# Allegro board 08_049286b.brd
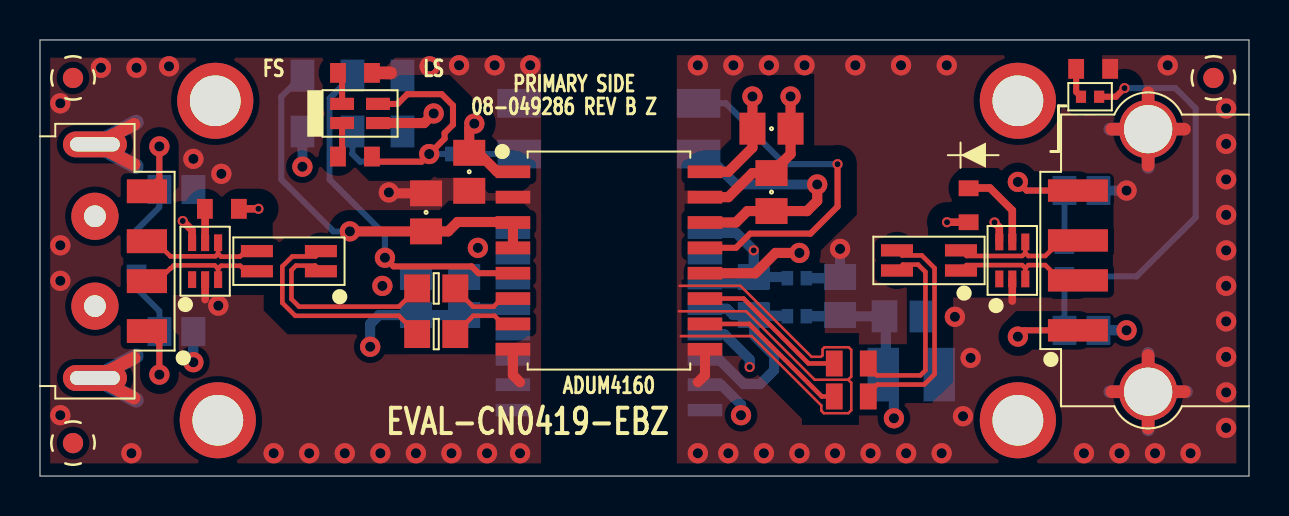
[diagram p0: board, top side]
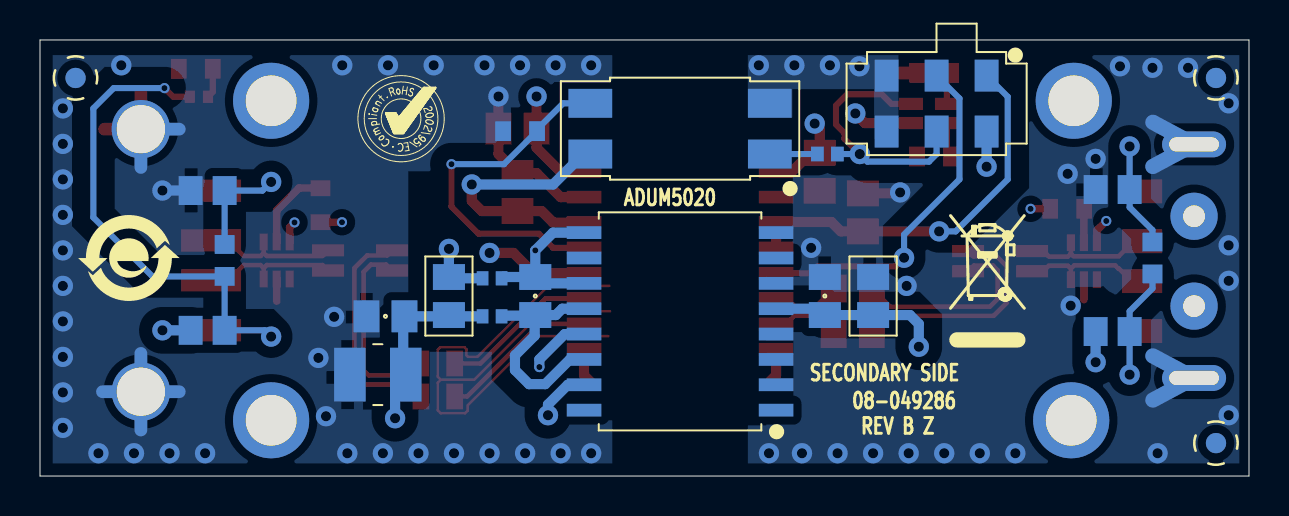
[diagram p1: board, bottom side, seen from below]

Outline 60.45 x 21.84 mm; copper layers: TOP, L2_GND, L3_VCC, BOTTOM. Coordinates in mm from the lower left corner of the outline.
Outline path: 0,21.84 0,0 60.45,0 60.45,21.84 0,21.84

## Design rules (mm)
constraint set DEFAULT: min track width 0.127
net group DP1: nets UNNAMED_2_CHOKE4P_I81_N2 UNNAMED_2_CHOKE4P_I81_N3
net group DP2: nets UNNAMED_2_CHOKE4P_I82_N1 UNNAMED_2_CHOKE4P_I82_N4
net group UNNAMED_2_ADUM4160_I1_DD: nets UNNAMED_2_ADUM4160_I1_DDNEG UNNAMED_2_ADUM4160_I1_DDPOS
net group UNNAMED_2_ADUM4160_I1_UD: nets UNNAMED_2_ADUM4160_I1_UDNEG UNNAMED_2_ADUM4160_I1_UDPOS
net group USB_DIFF_A: nets UNNAMED_2_CHOKE4P_I82_N2 UNNAMED_2_CHOKE4P_I82_N3
net group USB_DIFF_B: nets UNNAMED_2_CN4P2PSHLDV2_I66_N2 UNNAMED_2_CN4P2PSHLDV2_I66_N3

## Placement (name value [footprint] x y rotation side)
C1  0.001uF  [C0603]  4.83 10.92 270 bottom
C2  10uF  [C0805H53]  18.8 9.02 90 bottom
C3  0.1UF  [C0805]  21.21 9.02 90 bottom
C4  0.1UF  [C0805]  21.46 15.24 270 top
C5  0.1UF  [C0805]  19.3 13.21 270 top
C7  0.1UF  [C0805]  35.69 9.02 90 bottom
C8  0.1UF  [C0805]  36.58 17.4 0 top
C9  0.1UF  [C0805]  36.58 14.22 270 top
C10  10uF  [C0805H53]  40 9.02 90 bottom
C11  0.1UF  [C0805]  43.18 8 0 bottom
C12  100UF  [C1210-2]  43.56 5.08 180 bottom
C19  0.001uF  [C0603]  51.22 10.8 270 bottom
D1  RCLAMP0504FBTCT  [SC70-6H43]  8.26 10.76 0 top
D2  RCLAMP0504FBTCT  [SC70-6H43]  48.62 10.8 0 top
D3  LTV-817S-TA1  [SOP4H181]  28.45 17.4 90 bottom
D4  APHBM2012LVBDZGKC  [LED0805_4P]  16 18.16 180 top
DS1  SML-P11MTT86  [LED0402]  52.5 19 0 top
E1  220OHM  [L0805]  6.82 14.35 0 bottom
E2  220OHM  [L0805]  6.82 7.24 0 bottom
E3  220OHM  [L0805]  52.07 7.3 180 bottom
E4  220OHM  [L0805]  52.07 14.3 180 bottom
E5  1.8K AT 100MEGHZ  [L0402]  37.85 8 0 bottom
E6  1.8K AT 100MEGHZ  [L0402]  37.85 9.91 0 bottom
L1  260OHM AT 100MEGHZ  [LSML63W126H79]  12.45 10.76 90 top
L2  260OHM AT 100MEGHZ  [LSML63W126H79]  44.45 10.8 90 top
NOREF  -  []  -46.99 -67.82 0 top
NOREF#2  -  []  80.33 313.16 0 top
NOREF#3  -  []  -201.19 -168.4 0 top
NOREF#4  -  []  -39.37 155.07 0 top
NOREF#5  -  []  65.79 21.84 180 top
NOREF#6  -  []  0 10.74 0 top
NOREF#7  -  []  0 21.84 270 top
NOREF#8  -  [unnamed#2]  1.65 19.94 0 top
NOREF#9  -  [unnamed#2]  48.9 18.8 0 top
NOREF#10  -  []  8.89 2.79 0 top
NOREF#11  -  [unnamed#2]  8.89 2.79 0 top
NOREF#12  -  []  0 0 0 top
NOREF#13  -  []  60.45 0 0 top
NOREF#14  -  []  137.18 95.95 0 top
NOREF#15  -  [unnamed#2]  58.67 19.94 0 top
NOREF#16  -  []  0 0 0 top
NOREF#17  -  []  81.38 262.84 0 top
NOREF#18  -  []  0 21.84 0 top
NOREF#19  -  []  112.97 125.48 0 top
NOREF#20  -  []  8.89 2.79 0 top
NOREF#21  -  []  65.79 0 90 top
NOREF#22  -  []  60.45 0 90 top
NOREF#23  -  []  0 0 0 top
NOREF#24  -  []  28.45 35.48 0 top
NOREF#25  -  []  0 21.84 0 top
NOREF#26  -  [unnamed#2]  1.65 1.65 0 top
NOREF#27  -  []  -47.17 -68.07 0 top
NOREF#28  -  [unnamed#2]  48.9 2.79 0 top
NOREF#29  -  [unnamed#2]  8.76 18.8 0 top
NOREF#30  -  [unnamed#2]  1.65 1.65 180 bottom
NOREF#31  -  []  56.01 10.92 180 bottom
NOREF#32  -  [unnamed#2]  58.67 19.94 180 bottom
NOREF#33  -  []  13.28 6.5 180 bottom
NOREF#34  -  [unnamed#2]  1.65 19.94 180 bottom
P1  48037-2200  [CNMOLEX48037-2200]  2.75 10.76 90 top
P2  62900416021  [CNWURTH62900416021]  58.51 10.8 90 top
R1  10K  [R0603]  9.09 13.39 180 top
R2  24  [R0805#2]  19.81 9.4 0 top
R3  24  [R0805#2]  19.81 7.11 0 top
R4  24  [R0805]  40.56 5.64 0 top
R5  24  [R0805]  40.56 3.99 0 top
R6  10K  [R0603]  46.43 13.56 90 top
R7  301  [R0402]  21.08 16.13 0 bottom
R8  10K  [R0603]  36.45 17.27 180 bottom
R9  2.55K  [R0603]  15.75 20.19 0 top
R10  2.55K  [R0603]  15.75 16 0 top
R11  6.2K  [R0603]  52.66 20.4 0 top
S1  CL-SB-22A-11T  [SWSML335W138H217]  15.62 18.66 0 bottom
U1  ADUM4160BRWZ  [SO16WB]  28.45 10.79 270 top
U2  ADUM5020-5BRWZ  [SO16WB]  28.45 7.75 90 bottom

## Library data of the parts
C1 C19 = CAP: User Part Number: UPN; Tolerance: 5; alternate symbols: (C0603L_ALT); part number: CAP_SM-0.001UF,50V,5,E007908,C0603; tolerance: 5
C2 C10 = CAP: Tolerance: 10; User Part Number: UPN; alternate symbols: (); part number: CAP_SM-10UF,16V,10,E006166,C0805H53; tolerance: 10
C3-C5 C7-C9 C11 = CAP: Tolerance: 5; User Part Number: UPN; alternate symbols: (); part number: CAP_SM-0.1UF,50V,5,E031467,C0805; tolerance: 5
C12 = CAP: Tolerance: 20; User Part Number: UPN; alternate symbols: (); part number: CAP_SM-100UF,6.3V,20,E031805,C1210-2; tolerance: 20
D1 D2 = DIO6P_V9: User Part Number: UPN; Tolerance: N/A; alternate symbols: (); part number: DIO6P_V9_SM-RCLAMP0504FBTCT,5V,N/A,E031729,SC70-6H43; tolerance: N/A
D3 = DIOPHOTO_V4: User Part Number: UPN; Tolerance: N/A; alternate symbols: (); part number: DIOPHOTO_V4_SM-LTV-817S-TA1,35V,N/A,E033100,SOP4H181; tolerance: N/A
D4 = DIOLED_4P_V17: Tolerance: N/A; User Part Number: UPN; alternate symbols: (); part number: DIOLED_4P_V17_SM-APHBM2012LVBDZGKC,2.7V,N/A,E033594,LED0805_4P; tolerance: N/A
DS1 = DIOLED: User Part Number: UPN; Tolerance: N/A; alternate symbols: (); part number: DIOLED_SM-SML-P11MTT86,N/A,N/A,E014445,LED0402; tolerance: N/A
E1-E4 = FERRITE: User Part Number: UPN; Tolerance: 25; alternate symbols: (); part number: FERRITE_SM-220OHM,25,E017491,L0805; tolerance: 25
E5 E6 = FERRITE: User Part Number: UPN; Tolerance: 25; alternate symbols: (); part number: FERRITE_SM-1.8K AT 100MEGHZ,25,E027761,L0402; tolerance: 25
L1 L2 = CHOKE4P: User Part Number: UPN; Tolerance: 25; alternate symbols: (); part number: CHOKE4P_SM-260OHM AT 100MEGHZ,25,E027672,LSML63W126H79; tolerance: 25
P1 = CN4P_2PGND: User Part Number: UPN; Tolerance: N/A; alternate symbols: (); part number: CN4P_2PGND_SM-48037-2200,E028044,CNMOLEX48037-2200; tolerance: N/A
P2 = CN4P_2PSHLD_V2: Tolerance: N/A; User Part Number: UPN; alternate symbols: (); part number: CN4P_2PSHLD_V2_SM-62900416021,E024379,CNWURTH62900416021; tolerance: N/A
R1 R6 R8 = RES: User Part Number: UPN; Tolerance: 1; alternate symbols: (R0603L); part number: RES_SM-10K,E003671,1/10W,1,R0603; tolerance: 1
R2 R3 = RES: Tolerance: 1; User Part Number: UPN; alternate symbols: (); part number: RES_SM-24,E031456,1/8W,1,R0805; tolerance: 1
R4 R5 = RES: User Part Number: UPN; Tolerance: 1; alternate symbols: R0805L; part number: RES_SM-24,E031456,1/8W,1,R0805; tolerance: 1
R7 = RES: User Part Number: UPN; Tolerance: 1; alternate symbols: (R0402L); part number: RES_SM-301,E011195,1/16W,1,R0402; tolerance: 1
R9 R10 = RES: User Part Number: UPN; Tolerance: 1; alternate symbols: (); part number: RES_SM-2.55K,E032494,1/10W,1,R0603; tolerance: 1
R11 = RES: User Part Number: UPN; Tolerance: 1; alternate symbols: (R0603L); part number: RES_SM-6.2K,E010158,1/10W,1,R0603; tolerance: 1
S1 = SWDPDT_V5: User Part Number: UPN; Tolerance: N/A; alternate symbols: (); part number: SWDPDT_V5_SM-CL-SB-22A-11T,E033164,SWSML335W138H217; tolerance: N/A
U1 = ADUM4160: Tolerance: N/A; User Part Number: UPN; alternate symbols: (); part number: ADUM4160_SM-ADUM4160BRWZ,E012088,SO16WB; tolerance: N/A
U2 = ADUM5020: Tolerance: N/A; User Part Number: UPN; alternate symbols: (); part number: ADUM5020_SM-ADUM5020-5BRWZ,E028567,SO16WB; tolerance: N/A

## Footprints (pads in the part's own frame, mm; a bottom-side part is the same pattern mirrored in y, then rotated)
C0603
  rect 0.94x0.991 smd: 1(-0.8,0) 2(0.8,0)
C0805
  rect 1.295x1.6 smd: 1(-0.953,0) 2(0.953,0)
C0805H53
  rect 1.295x1.6 smd: 1(-0.953,0) 2(0.953,0)
C1210-2
  rect 1.575x2.692 smd: 1(-1.397,0) 2(1.397,0)
CNMOLEX48037-2200
  round 2.362 hole 1.092 unplated: (-2.25,0) (2.25,0)
  rect 1.194x2.007 smd: 1(-3.5,-2.6) 2(-1,-2.6) 3(1,-2.6) 4(3.5,-2.6)
  oval 1.295x3.2 hole 0.711x2.489: G1(-5.85,0) G2(5.85,0)
CNWURTH62900416021
  rect 1.118x2.997 smd: 1(-3.5,6.61) 2(-1,6.61) 3(1,6.61) 4(3.5,6.61)
  round 2.921 hole 2.413: SH1(-6.575,3.1) SH2(6.575,3.1)
L0402
  rect 0.584x0.711 smd: 1(-0.475,0) 2(0.475,0)
L0805
  rect 1.194x1.448 smd: 1(-0.85,0) 2(0.85,0)
LED0402
  rect 0.508x0.61 smd: A(0.454,0) C(-0.454,0)
LED0805_4P
  rect 1.194x0.61 smd: 1(-0.897,-0.48) 2(0.897,-0.48) 3(0.897,0.48) 4(-0.897,0.48)
LSML63W126H79
  rect 0.61x1.6 smd: 1(-0.505,-1.6) 2(-0.505,1.6) 3(0.505,1.6) 4(0.505,-1.6)
R0402
  rect 0.635x0.737 smd: 1(-0.5,0) 2(0.5,0)
R0603
  rect 0.787x0.991 smd: 1(-0.85,0) 2(0.85,0)
R0805
  rect 0.838x1.295 smd: 1(-0.85,0) 2(0.85,0)
R0805#2
  rect 1.295x1.397 smd: 1(-0.953,0) 2(0.953,0)
SC70-6H43
  rect 0.406x0.838 smd: 1(-0.65,-0.925) 2(0,-0.925) 3(0.65,-0.925) 4(0.65,0.925) 5(0,0.925) 6(-0.65,0.925)
SO16WB
  rect 0.635x1.727 smd: 1(-4.445,-4.801) 2(-3.175,-4.801) 3(-1.905,-4.801) 4(-0.635,-4.801) 5(0.635,-4.801) 6(1.905,-4.801) 7(3.175,-4.801) 8(4.445,-4.801) 9(4.445,4.801) 10(3.175,4.801) 11(1.905,4.801) 12(0.635,4.801) 13(-0.635,4.801) 14(-1.905,4.801) 15(-3.175,4.801) 16(-4.445,4.801)
SOP4H181
  rect 1.448x2.184 smd: 1(-1.27,-4.487) 2(1.27,-4.487) 3(1.27,4.487) 4(-1.27,4.487)
SWSML335W138H217
  rect 1.194x1.6 smd: 1(-2.5,-1.4) 2(0,-1.4) 3(2.5,-1.4) 4(-2.5,1.4) 5(0,1.4) 6(2.5,1.4)
unnamed#2
  round 1.016 smd: (0,0)

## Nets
5V_BUS: C2.1 C3.1 C4.1 D1.6 D4.4 E2.2(N2) R1.1 S1.4 U1.1 U2.5
5V_ISO_BUS: C8.1 C10.1 C11.1 C12.2(N2) D2.6 E3.1 E5.2(N2) R6.1 U1.16
AGND: C7.2(N2) E6.1 U2.9 U2.11 U2.13 U2.15
GND: C2.2(N2) C3.2(N2) C4.2(N2) C5.1 D1.2 D3.2 E1.2(N2) P1.G1 P1.G2 R9.2(N2) S1.3 S1.6(NO2) U1.2 U1.8 U2.2 U2.3 U2.4 U2.6 U2.8
GND_ISO: C8.2(N2) C9.1 C10.2(N2) C11.2(N2) C12.1 D2.2 E4.1 E6.2(N2) P2.SH1 P2.SH2(N6) R8.1 R11.2(N2) U1.9 U1.15
UNNAMED_2_ADUM4160_I1_DDNEG: R4.1 U1.11
UNNAMED_2_ADUM4160_I1_DDPOS: R5.1 U1.10
UNNAMED_2_ADUM4160_I1_PDEN: C5.2(N2) S1.1 U1.3 U1.4
UNNAMED_2_ADUM4160_I1_PIN: C9.2(N2) D3.4 U1.12 U1.14(VDD2)
UNNAMED_2_ADUM4160_I1_SPU: S1.2 U1.5
UNNAMED_2_ADUM4160_I1_UDNEG: R2.2(N2) U1.6
UNNAMED_2_ADUM4160_I1_UDPOS: R3.2(N2) U1.7
UNNAMED_2_ADUM5020_I2_VISO: C7.1 E5.1 U2.12 U2.14(VSEL)
UNNAMED_2_CAP_I84_N1: C1.1 E1.1 P1.4(N4)
UNNAMED_2_CAP_I84_N2: C1.2(N2) E2.1 P1.1
UNNAMED_2_CAP_I85_N1: C19.1 E4.2(N2) P2.4
UNNAMED_2_CAP_I85_N2: C19.2(N2) DS1.A(P) E3.2(N2) P2.1
UNNAMED_2_CHOKE4P_I81_N2: L2.2 R4.2(N2)
UNNAMED_2_CHOKE4P_I81_N3: L2.3 R5.2(N2)
UNNAMED_2_CHOKE4P_I82_N1: L1.1 R2.1
UNNAMED_2_CHOKE4P_I82_N2: D1.3 L1.2 P1.2
UNNAMED_2_CHOKE4P_I82_N3: D1.4 L1.3 P1.3
UNNAMED_2_CHOKE4P_I82_N4: L1.4(N4) R3.1
UNNAMED_2_CN4P2PSHLDV2_I66_N2: D2.3 L2.1 P2.2
UNNAMED_2_CN4P2PSHLDV2_I66_N3: D2.4 L2.4(N4) P2.3
UNNAMED_2_DIO6PV9_I78_VDD: D1.5(VDD) R1.2(N2)
UNNAMED_2_DIO6PV9_I79_VDD: D2.5(VDD) R6.2(N2)
UNNAMED_2_DIOLED4PV17_I106_A1: D4.1 R7.1 R10.2(N2) S1.5
UNNAMED_2_DIOLED4PV17_I106_C1: D4.2 R9.1
UNNAMED_2_DIOLED4PV17_I106_C2: D4.3(C2) R10.1
UNNAMED_2_DIOLED_I109_N: DS1.C R11.1
UNNAMED_2_DIOPHOTOV4_I98_A: D3.1 R7.2(N2)
UNNAMED_2_DIOPHOTOV4_I98_E: D3.3(E) R8.2(N2) U1.13

Pads without a net: D1 1; D2 1; U2 1 7 10 16

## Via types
v1: diameter 1.016, hole 0.508, TOP to BOTTOM, 80 vias
v2: diameter 0.508, hole 0.305, TOP to BOTTOM, 8 vias

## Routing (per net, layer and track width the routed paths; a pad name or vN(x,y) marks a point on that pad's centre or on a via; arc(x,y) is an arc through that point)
5V_BUS: length 21.3
  TOP w0.381: R1.1 v2(10.92,13.39) ; v2(7.14,12.78) 7.61,12.31 D1.6
  TOP w0.508: U1.1 22.86,15.24 21.91,16.19 C4.1 21.46,17.4 v1(21.72,17.65) ; v1(19.69,18.16) 19.21,17.68 D4.4
  BOTTOM w0.508: U2.5 21.53,8.38 C3.1 C2.1 16.95,8.06 16.51,7.62 v1(16.51,6.48) ; S1.4 v1(13.12,15.49) ; E2.2 v1(7.67,5.7)
5V_ISO_BUS: length 18.4
  TOP w0.381: v2(47.73,12.7) 47.73,12.7 47.97,12.46 D2.6 ; R6.1 v2(45.35,12.71)
  TOP w0.508: v1(35.62,19.01) C8.1 35.62,16.45 34.42,15.24 U1.16
  BOTTOM w0.508: E5.2 39.94,8 C10.1 40.07,8 C11.1 42.29,7.94 42.29,5.21 C12.2 42.7,4.55 v1(42.7,2.9) ; E3.1 v1(54.33,7.3)
AGND: length 14.3
  BOTTOM w0.508: C7.2 35.37,9.65 U2.11 ; C7.2 37.31,9.97 E6.1 ; C7.2 v2(35.69,11.3) 34.8,12.19 U2.9 ; U2.13 34.21,7.11 35.48,5.84 v2(35.48,5.46) ; U2.15 34.06,4.57 35.05,3.58 v1(35.05,3.05)
GND: length 23.7
  TOP w0.381: D1.2 8.26,8.84
  TOP w0.508: C5.1 17.49,14.16 v1(17.44,14.21) ; U1.8 23.65,5.05 24,4.7
  TOP w0.635: 4.7,15.61 P1.G2 4.7,17.62 ; R9.2 17.53,20.19 ; 4.7,3.91 P1.G1 4.7,5.92
  BOTTOM w0.762: 4.8,17.72 P1.G2 4.8,15.51 ; 4.8,3.81 P1.G1 4.8,6.02
  vias: v1(1.02,18.67) v1(1.02,11.56) v1(1.02,9.78) v1(1.02,3.05) v1(3.05,20.45) v1(4.57,1.14) v1(4.83,20.45) v1(6.45,20.52) v1(7.67,15.89) v1(8.92,8.53) v1(9.07,15.14) v1(11.68,1.14) v1(13.46,1.14) v1(15.24,1.14) v1(17.02,1.14) v1(17.12,9.53) v1(18.8,1.14) v1(19.48,20.52) v1(20.57,1.14) v1(20.95,20.57) v1(21.89,11.43) v1(22.35,1.14) v1(22.73,20.57) v1(24,1.14) v1(24.51,20.57)
GND_ISO: length 75.4
  TOP w0.127: 40.41,4.83 40.56,4.98 40.56,6.32 40.44,6.45 39.23,6.45 39.13,6.36 39.13,6.05 39.06,5.97 38.58,5.97 35.03,9.53 31.98,9.53 ; 40.41,4.83 38.73,4.83 35.31,8.26 31.95,8.26 ; 40.41,4.83 40.56,4.67 40.56,3.3 40.42,3.15 39.19,3.15 39.07,3.28 39.07,3.54 35.59,7.01 32.04,7.01
  TOP w0.381: D2.2 48.62,8.76
  TOP w0.508: v1(37.53,19.01) C8.2 37.53,16.13 C9.1 35.62,15.18 34.42,13.97 U1.15 ; U1.9 33.25,5.05 32.89,4.7
  TOP w0.635: 53.59,17.38 P2.SH2 ; P2.SH2 57.22,17.38 ; P2.SH2 55.41,19.19 ; P2.SH2 55.41,15.56 ; 55.41,2.41 P2.SH1 ; P2.SH1 53.59,4.23 ; P2.SH1 57.22,4.23 ; P2.SH1 55.41,6.04
  BOTTOM w0.508: E6.2 39.94,9.91 C10.2 v1(40,11.38) ; E4.1 v1(54.33,14.3)
  BOTTOM w0.635: 55.41,2.31 P2.SH1 ; P2.SH1 55.41,6.14 ; P2.SH1 57.33,4.23 ; P2.SH1 53.49,4.23 ; 53.49,17.38 P2.SH2 55.41,15.46
  vias: v1(32.89,20.57) v1(32.89,1.14) v1(34.42,1.14) v1(34.67,20.57) v1(36.2,1.14) v1(36.45,20.57) v1(37.97,1.14) v1(38.23,20.57) v1(39.75,1.14) v1(40.77,20.57) v1(41.53,1.14) v1(43.05,20.57) v1(43.31,1.14) v1(45.09,1.14) v1(45.34,20.57) v1(45.75,7.98) v1(46.15,3) v1(46.53,5.92) v1(52.2,1.14) v1(53.98,1.14) v1(55.75,1.14) v1(56.39,20.57) v1(57.53,1.14) v1(59.31,18.41) v1(59.31,16.64) v1(59.31,14.86) v1(59.31,13.08) v1(59.31,11.3) v1(59.31,9.53) v1(59.31,7.75) v1(59.31,5.97) v1(59.31,4.19) v1(59.31,2.41)
UNNAMED_2_ADUM4160_I1_DDNEG: length 7.8
  TOP w0.229: R4.1 38.43,5.64 35.18,8.89 U1.11
UNNAMED_2_ADUM4160_I1_DDPOS: length 8
  TOP w0.229: U1.10 35.46,7.62 39.09,3.99 R5.1
UNNAMED_2_ADUM4160_I1_PDEN: length 19.8
  TOP w0.508: v1(15.49,12.26) C5.2 20.41,12.26 20.88,12.73 23.62,12.73 U1.3 U1.4
  BOTTOM w0.305: S1.1 12.07,19 12.07,14.86 14.67,12.26 v1(15.49,12.26)
UNNAMED_2_ADUM4160_I1_PIN: length 18.6
  TOP w0.508: v1(37.97,11.18) 36.78,11.18 35.76,10.16 U1.12 ; U1.14 34.8,12.7 35.37,13.27 C9.2 38.35,13.27 38.86,13.78 v1(38.86,14.61)
  BOTTOM w0.508: D3.4 33.27,16.13 34.8,14.61 v1(38.86,14.61)
UNNAMED_2_ADUM4160_I1_SPU: length 17.5
  TOP w0.305: v1(17.25,10.93) 17.68,10.5 21.58,10.5 21.92,10.16 U1.5
  BOTTOM w0.305: S1.2 14.48,18.91 14.48,14.86 17.25,12.09 v1(17.25,10.93)
UNNAMED_2_ADUM4160_I1_UDNEG: length 3.4
  TOP w0.229: U1.6 23.09,8.89 22.68,8.48 21.66,8.48 20.76,9.38 R2.2
UNNAMED_2_ADUM4160_I1_UDPOS: length 3.4
  TOP w0.229: R3.2 20.76,7.13 21.66,8.03 22.73,8.03 23.14,7.62 U1.7
UNNAMED_2_ADUM5020_I2_VISO: length 11.7
  BOTTOM w0.508: 35.72,8.03 37.34,8.03 E5.1 ; 35.72,8.03 35.72,7.03 36.7,6.05 36.7,5.31 36,4.6 35.19,4.6 33.95,5.84 U2.14 ; 35.72,8.03 C7.1 34.66,8.06 34.34,8.38 U2.12
UNNAMED_2_CAP_I84_N1: length 7.8
  TOP w0.305: v1(5.97,16.51) 5.97,14.88 P1.4
  BOTTOM w0.305: v1(5.97,16.51) E1.1 5.97,13.46 4.83,12.32 C1.1
UNNAMED_2_CAP_I84_N2: length 8
  TOP w0.305: P1.1 5.97,6.64 v1(5.97,5.08)
  BOTTOM w0.305: C1.2 4.83,9.4 5.97,8.26 E2.1 v1(5.97,5.08)
UNNAMED_2_CAP_I85_N1: length 8.4
  TOP w0.305: P2.4 49.33,14.3 v1(48.9,14.73)
  BOTTOM w0.305: C19.1 E4.2 49.33,14.3 v1(48.9,14.73)
UNNAMED_2_CAP_I85_N2: length 27
  TOP w0.305: v1(48.9,6.98) 49.21,7.3 P2.1 ; DS1.A 53.8,19 v2(54.23,19.43)
  BOTTOM w0.305: v2(54.23,19.43) 56.77,19.43 57.79,18.41 57.79,12.95 54.83,10 C19.2 E3.2 49.21,7.3 v1(48.9,6.98)
UNNAMED_2_CHOKE4P_I81_N2: length 9.9
  TOP w0.229: R4.2 41.41,5.47 41.85,5.04 44.02,5.04 44.27,5.3 44.27,10.22 43.9,10.59 43.15,10.59 L2.2
UNNAMED_2_CHOKE4P_I81_N3: length 11.4
  TOP w0.229: R5.2 41.41,4.13 41.87,4.58 44.21,4.58 44.73,5.11 44.73,10.41 44.09,11.05 43.11,11.05 L2.3
UNNAMED_2_CHOKE4P_I82_N1: length 10
  TOP w0.229: R2.1 17.95,8.48 12.95,8.48 12.57,8.86 12.57,10.31 12.8,10.54 13.76,10.54 L1.1
UNNAMED_2_CHOKE4P_I82_N2: length 6.6
  TOP w0.229: D1.3 8.9,10.39 ; 8.9,10.39 9.05,10.53 10.01,10.53 10.29,10.26 L1.2 ; 8.9,10.39 8.74,10.55 6.69,10.55 6.53,10.39 6.5,10.39 5.88,9.76 P1.2
UNNAMED_2_CHOKE4P_I82_N3: length 6.6
  TOP w0.229: 8.9,11.14 9.05,10.99 10,10.99 10.28,11.27 L1.3 ; 8.9,11.14 8.77,11.01 6.52,11.01 5.76,11.76 P1.3 ; 8.9,11.14 D1.4
UNNAMED_2_CHOKE4P_I82_N4: length 11.5
  TOP w0.229: L1.4 13.78,11 12.61,11 12.12,10.5 12.12,8.68 12.76,8.03 17.95,8.03 R3.1
UNNAMED_2_CN4P2PSHLDV2_I66_N2: length 6.9
  TOP w0.229: L2.1 46.32,10.57 49.11,10.57 49.27,10.41 ; P2.2 51.03,9.8 50.27,10.57 49.42,10.57 49.27,10.41 ; D2.3 49.27,10.41
UNNAMED_2_CN4P2PSHLDV2_I66_N3: length 7
  TOP w0.229: D2.4 49.27,11.18 ; 49.27,11.18 49.11,11.02 46.33,11.02 L2.4 ; 49.27,11.18 49.42,11.02 50.27,11.02 51.04,11.8 P2.3
UNNAMED_2_DIO6PV9_I78_VDD: length 1.7
  TOP w0.381: R1.2 8.26,13.37 D1.5
UNNAMED_2_DIO6PV9_I79_VDD: length 4.2
  TOP w0.381: D2.5 48.62,13.31 47.5,14.43 46.44,14.43 R6.2
UNNAMED_2_DIOLED4PV17_I106_A1: length 16.6
  TOP w0.305: D4.1 17.88,18.64 18.36,19.13 20.09,19.13 20.65,18.56 20.65,17.6 20.23,17.18 20.23,16.9 v1(19.46,16.13) 19.08,15.75 16.85,15.75 R10.2
  BOTTOM w0.305: S1.5 15.62,16.13 16,15.75 19.08,15.75 v1(19.46,16.13) R7.1
UNNAMED_2_DIOLED4PV17_I106_C1: length 1.6
  TOP w0.305: R9.1 15.11,19.99 D4.2
UNNAMED_2_DIOLED4PV17_I106_C2: length 1.8
  TOP w0.305: D4.3 15.11,16.21 R10.1
UNNAMED_2_DIOLED_I109_N: length 1.5
  TOP w0.305: R11.1 51.81,19.24 DS1.C
UNNAMED_2_DIOPHOTOV4_I98_A: length 2.4
  BOTTOM w0.305: R7.2 D3.1
UNNAMED_2_DIOPHOTOV4_I98_E: length 17.9
  TOP w0.305: U1.13 34.8,11.43 35.51,12.14 38.53,12.14 39.88,13.49 v2(39.88,15.62)
  BOTTOM w0.305: D3.3 34.29,18.67 35.6,17.36 R8.2 37.25,15.62 v2(39.88,15.62)

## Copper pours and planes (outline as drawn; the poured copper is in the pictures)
5V_BUS on L3_VCC: 0.51,0.64 0.51,21.08 25.15,21.08 25.15,0.64
5V_ISO_BUS on L3_VCC: 31.75,0.64 31.75,5.59 39.5,5.59 40.89,6.98 40.89,14.99 39.62,16.26 31.75,16.26 31.75,21.08 59.82,21.08 59.82,0.64
AGND on L3_VCC (solid shape): 35.69,11.48 35.87,11.3 35.69,11.13 35.51,11.13 35.31,10.92 35.31,5.71 35.38,5.64 35.56,5.64 35.66,5.54 35.66,5.36 35.56,5.26 35.38,5.26 35.31,5.18 35.31,3.05 35.05,2.79 34.8,3.05 34.8,11.18 35.1,11.48
GND on TOP: 0.51,0.64 0.51,20.96 15.49,20.96 15.49,19.71 16.46,19.71 16.46,19.28 17.32,19.28 17.37,19.23 17.75,19.23 18.08,19.56 18.08,19.89 18.06,19.86 17.32,19.86 17.32,20.52 17.75,20.96 25.06,20.96 25.06,0.64 ; 9 cut-outs
GND on BOTTOM: 0.48,0.64 0.48,21.08 15.67,21.08 15.67,16.41 17.53,16.41 17.53,21.08 25.15,21.08 25.15,17.96 22.83,17.96 22.83,19.38 18.75,19.38 18.75,18.08 18.72,18.08 18.72,16.76 19.38,16.76 19.38,17.09 21.56,17.09 21.56,17.93 22.56,17.93 22.56,17.6 22.12,17.6 22.12,17.56 22.1,17.44 22.07,17.33 22.08,17.24 22.16,17.2 22.56,17.2 22.56,17.17 25.15,17.17 25.15,15.06 22.81,15.06 22.81,12.55 24.13,12.55 24.13,11.91 22.81,11.91 22.81,11.51 24.13,11.51 24.13,10.41 22.48,10.41 22.48,9.98 24.13,9.98 24.13,6.78 22.78,6.78 22.78,6.17 24.13,6.17 24.13,5.54 22.78,5.54 22.78,4.9 24.13,4.9 24.13,4.27 22.78,4.27 22.78,3.81 24.13,3.81 24.13,2.54 25.15,2.54 25.15,0.64 ; 6 cut-outs
GND on L2_GND: 0.51,0.64 0.51,20.96 25.15,20.96 25.15,0.64
GND_ISO on TOP: 31.84,0.64 31.84,21.08 59.82,21.08 59.82,0.64 ; 11 cut-outs
GND_ISO on BOTTOM: 31.84,0.64 31.84,2.79 33.66,2.79 33.66,15.11 31.84,15.11 31.84,16.89 34.42,16.89 34.42,17.65 31.84,17.65 31.84,21.08 59.82,21.08 59.82,0.64 ; 11 cut-outs
GND_ISO on L2_GND: 59.82,21.08 59.82,0.64 31.75,0.64 31.75,21.08 ; 1 cut-out

Small or netless copper shapes (teardrops, artwork), in the pictures only: 1 on L3_VCC

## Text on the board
Ref Des/Silkscreen Bottom: 08-049286 | REV B Z | SECONDARY SIDE | ADUM5020
Ref Des/Silkscreen Top: 08-049286 REV B Z | PRIMARY SIDE | FS | LS | ADUM4160 | EVAL-CN0419-EBZ
PAGE_OUTLINE: B | AS PER ECR-079649 | 31AUG18 | T.CABILDO | EVALUATION BOARD Z
DIMENSION: (REF) | DIA MAX
User.9: L2 GND | 08-      -07
User.10: L3 VCC | 08-      -08
User.15: IMPEDANCE CONTROLLED SPACING = 0.009" | ROHS COMPLIANCE NOTE: | PER IPC-4552 LATEST REVISION | HOMOGENOUS MATERIALS IN THIS BOARD SHALL BE COMPLIANT | THE EU RoHS DIRECTIVE 2002/95/EC | ENIG (ELECTROLESS NICKEL/IMMERSION GOLD)
User.26: B | AS PER ECR-079649 | 31AUG18 | T.CABILDO | EVAL BOARD Z | CUSTOMER EVALUATION BOARD Z
User.39: FL1 | FL2 | PRIMARY SIDE
User.41: FIGURE | SIZE | 12.0 | 20.0 | 95.0 | 43.0 | 100.0 | 98.0x28.0 | DRILL CHART: TOP to BOTTOM | FINISHED HOLES IN MILS | PLATED | NON-PLATED | QTY | 8 | 80 | 2 | 4 | TOLERANCE/NOTES
